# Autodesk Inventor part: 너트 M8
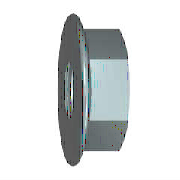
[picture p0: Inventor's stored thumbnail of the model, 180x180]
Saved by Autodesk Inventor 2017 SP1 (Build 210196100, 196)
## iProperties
Created: 2015-09
Part Number: 너트 M8
Material: 스테인리스강
Description: 플랜지붙이 6각 너트 - 일반 스레드
Document SubType Name: Modeling
Standard: ISO 4161
Designer: mduedu
Standard Revision: 2판 1999-03-15
Standards Organization: ISO
Language: ko-KR
Size Designation: M8
Categories: <MemberInstance><Categories><Category DisplayName="조임쇠" InternalName="e4da775c-781d-43d5-af7c-5136215cf5a6" Mnemonic="FSTN"><Category DisplayName="너트" InternalN
Density: 8.08 g/cm^3
Appearance: 강철
Author: mduedu
IsCustomPart: 1
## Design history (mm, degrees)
sketch "스케치1"
  geometry: L1 (-1.844, 0)-(9.641, 0) reference; L2 (3.107, 6.5)-(2.288, 8.257); L3 (3.107, 6.5)-(8, 6.5); L4 (8, 6.5)-(8, 0); L5 (3.107, 6.5)-(3.107, 0); L6 (0, -1.835)-(0, 11.01) reference; A1 r 1.2 centre (1.2, 7.75) between (2.288, 8.257) and (0, 7.75); 1 further point
  constraints: 8 end point, 3 point on line, 2 perpendicular, 2 point on circle, 2 tangent, 1 centre point, 1 parallel
  dimensions: "d2" = 13 diameter of L3 L1 (= SW); "d4" = 17.9 dimension on A1 L1 (= LADI); "d5" = 1.2 radius of A1 (= PHH); "d15" = 8 distance between parallel lines of L4 L6 (= KOH); "d16" = 25 deg angle of L6 L2 (= KEWI)
revolve "링" sketch "스케치1" stored, may be unused: angle "d8" = 90 deg
sketch "스케치2"
  geometry: L1 (-6.5, -3.753)-(-6.5, 3.753); L2 (-6.5, 3.753)-(0, 7.506); L3 (0, 7.506)-(6.5, 3.753); L4 (6.5, 3.753)-(6.5, -3.753); L5 (6.5, -3.753)-(0, -7.506); L6 (0, -7.506)-(-6.5, -3.753); C1 r 4.9 at (0, 0); C2 r 7.75 at (0, 0) reference; 1 further point
  constraints: 12 end point, 1 centre point, 1 coincident, 1 vertical, 11 other
  dimensions: "d6" = 15.01111 distance of L5.end L2.end (= 1.1547 x SW)
extrude "본체" join sketch "스케치2" distance "d7" = 8 (= KOH); taper "d9" = 0 deg
sketch "스케치3"
  geometry: L1 (2.638, 7.506)-(8, 7.506) reference; L2 (8, 3.753)-(8, 7.506) reference; L3 (0, -7.75)-(0, 7.75) reference; L4 (-1.6, 0)-(9.6, 0) reference; L5 (7.419, 7.506)-(8, 6.5)
  constraints: 2 end point, 2 point on line
  dimensions: "d10" = 30 deg angle of L2 L5 (= ANG1); "d11" = 13 diameter of L5.end L4 (= SW0)
revolve "모따기1" sketch "스케치3" stored, may be unused: angle "d24" = 90 deg
sketch "스케치4"
  geometry: C1 r 7.75 at (0, 0) reference; 1 further point
  constraints: 1 coincident
hole "스레드" sketch "스케치4" at (0, 0) diameter "d25" = 6.647; stored, may be unused: countersink angle "d29" = 82 deg, drill point angle "d31" = 118 deg; dims "d26" = 6, "d27" = 4, "d28" = 2, "d30" = 8
workaxis "Work Axis1"
workplane "Work Plane1"
body "Solid1"
chamfer "모따기2" distance "d12" = 0.67658 (= -0.5 x GD1 + 0.5 x NND); stored, may be unused: angle "d13" = 30 deg, second distance "d46" = 0.67658 (= -0.5 x GD1 + 0.5 x NND)
chamfer "모따기3" distance "d51" = 0.67658 (= -0.5 x GD1 + 0.5 x NND); stored, may be unused: second distance "d52" = 2, angle "d53" = 45 deg
other parameters: "ANG1" = 30 deg [user parameter; used in 1 equation term], "KEWI" = 25 deg [user parameter; used in 1 equation term], "NND" = 8 [user parameter; used in 4 equation terms], "LADI" = 17.9 [user parameter; used in 2 equation terms], "SW" = 13 [user parameter; used in 3 equation terms], "PHH" = 1.2 [user parameter; used in 3 equation terms], "KOH" = 8 (= NND) [user parameter; used in 2 equation terms], "SW0" = 13 [user parameter; used in 1 equation term], "GD1" = 6.64684 (computed from THREADDIA, PTC, TOA) [user parameter; used in 3 equation terms], "d1" = 17.9 (= LADI), "d3" = 1.2 (= PHH), "d45" = 0, "d47" = 0, "d49" = 0, "d54" = 0, "GUL" = 0.67658 (= 0.541266 x PTC) [user parameter], "TPU" = 8 (computed from PTC) [user parameter], "RR" = 1.2 (= PHH) [user parameter], "THREADDIA" = 8 [user parameter; used in 1 equation term], "TOA" = 30 deg [user parameter; used in 1 equation term], "PTC" = 1.25 [user parameter; used in 4 equation terms], "GAL" = 0.67658 (= 0.541266 x PTC) [user parameter], "E0" = 15.015 (= 1.155 x SW) [user parameter]
